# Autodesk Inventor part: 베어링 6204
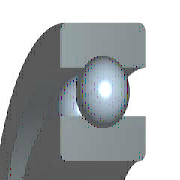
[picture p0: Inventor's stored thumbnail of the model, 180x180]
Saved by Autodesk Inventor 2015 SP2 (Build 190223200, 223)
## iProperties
IsCustomPart: 0
Manager: KYOUNG IL JANG
Company: 한국ATC센터
Created: 2009-02
Part Number: 베어링 6204
Material: Steel, Mild
Description: 깊은 그루브 볼 베어링
Document SubType Name: Modeling
Standard: KS B 2023
Standards Organization: KS
Language: ko-KR
Size Designation: 6204 - 20 x 47 x 14
Categories: <MemberInstance><Categories><Category DisplayName="샤프트 부품" InternalName="7f7aeb1f-a693-4053-b835-cee3144e0d98" Mnemonic="SHFT"><Category DisplayName="베어링" Inter
Density: 1 g/cm^3
Checked By: KYOUNG IL JANG
Vendor: CBT Solutions
Designer: KYOUNG IL JANG
Appearance: _시험-파란색 크롬
Author: KYOUNG IL JANG
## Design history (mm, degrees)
sketch "스케치" dims "d0" = 7.02 (= -0.26 x WD + 0.26 x BD)
  geometry: L1 (3.49, 16.75)-(10.51, 16.75); L2 (7, 16.75)-(7, 13.24); L3 (7, 16.75)-(7, 20.26); L4 (4.392, 14.401)-(0, 14.401); L5 (0, 10)-(14, 10); L6 (4.392, 19.099)-(0, 19.099); L7 (0, 23.5)-(14, 23.5); L8 (14, 10)-(14, 14.401); L9 (9.608, 14.401)-(14, 14.401); L10 (9.608, 19.099)-(14, 19.099); L11 (14, 23.5)-(14, 19.099); L12 (-1.4, 0)-(8.4, 0) reference; L13 (0, -0.3)-(0, 5.3) reference
  constraints: 22 end point, 4 point on line, 2 collinear, 2 perpendicular, 2 symmetric about line, 1 midpoint, 1 parallel, 14 other
  dimensions: "d9" = 20 diameter of L5 L12 (= WD); "d11" = 47 diameter of L7 L12 (= BD); "d12" = 14 distance between parallel lines of L8 L13 (= KB); "d13" = 28.802 diameter of L9 L12 (= 0.326 x BD + 0.674 x WD)
revolve "본체" stored, may be unused: angle "d6" = 90 deg
revolve "볼" stored, may be unused: angle "d7" = 90 deg
pattern_circular "IDS_ARRAYBALL[SIMPL:T]" dims angle "d3" = 360 deg
body "Solid1"
fillet "모깎기1" dims "d1" = 1 (= KRS)
other parameters: "WD" = 20 [user parameter; used in 5 equation terms], "BD" = 47 [user parameter; used in 5 equation terms], "KB" = 14 [user parameter; used in 1 equation term], "KRS" = 1 [user parameter; used in 1 equation term], "d4" = 0, "d5" = 0, "d8" = 0, "d14" = 0, "d15" = 0, "BBA" = 0 [user parameter], "BC0" = 6550000 [user parameter], "BC" = 1.27e+07 [user parameter], "BR" = 23.5 (= 0.5 x BD) [user parameter]
